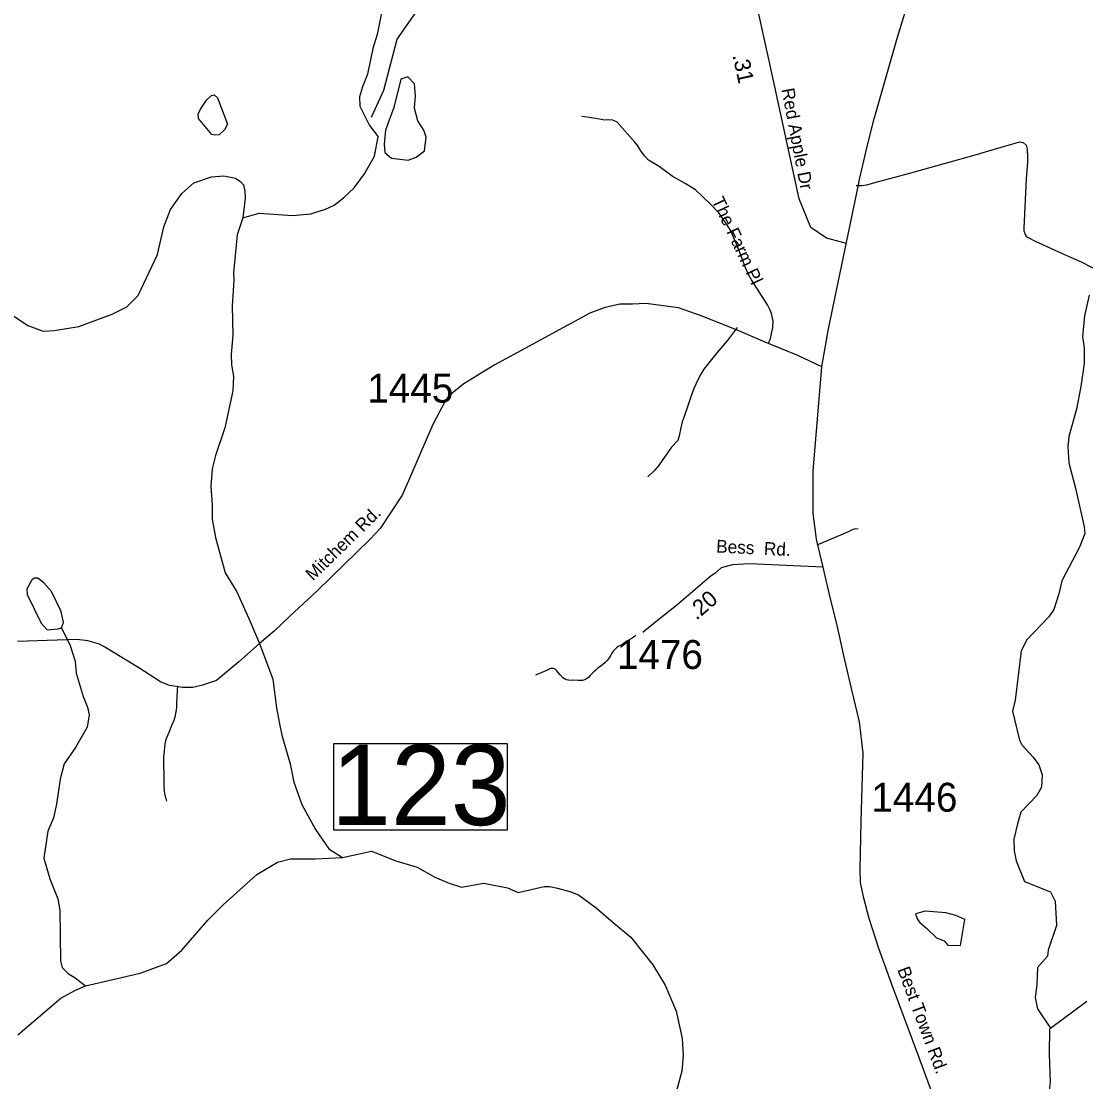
# Model space of a CAD drawing. Extents: x 1268485 to 1426702, y 514839 to 616766.
# Drawn here: x 1317709 to 1323145, y 579327 to 584743 of the extents above; entities that cross this region are included whole.
import ezdxf

# ---------------------------------------------------------------- set-up
doc = ezdxf.new("R2010")
doc.units = 0
for name, color, linetype in [('Old_Level_10', 7, 'Continuous'), ('Old_Level_11', 7, 'Continuous'), ('Old_Level_17', 7, 'Continuous'), ('Old_Level_31', 7, 'Continuous'), ('Old_Level_32', 7, 'Continuous'), ('Old_Level_35', 7, 'Continuous'), ('Old_Level_50', 7, 'Continuous'), ('Old_Level_59', 7, 'Continuous'), ('Old_Level_62', 7, 'Continuous'), ('Old_Level_8', 7, 'Continuous')]:
    doc.layers.add(name, color=color, linetype=linetype)

msp = doc.modelspace()

# ---------------------------------------------------------------- linework, layer by layer
at = {"layer": 'Old_Level_31'}
msp.add_line((1318926.085, 581564.107), (1318926.085, 581564.107), dxfattribs=at)
msp.add_lwpolyline([(1320191.896, 581051.986), (1319302.932, 581051.986), (1319302.932, 580614.063), (1320191.896, 580614.063), (1320191.896, 581051.986)], dxfattribs=at)
at = {"layer": 'Old_Level_32'}
for points in [[(1321797.997, 582978.324), (1321831.203, 583171.729), (1321983.009, 583898.519), (1321990.349, 583934.525), (1322028.373, 584103.643), (1322063.633, 584244.803), (1322183.303, 584662.401), (1322279.87, 584980.061), (1322315.078, 585068.895), (1322350.496, 585143.263), (1322444.891, 585301.092), (1322460.199, 585319.471), (1322477.038, 585333.257), (1322625.673, 585434.483), (1322656.143, 585455.787), (1322668.712, 585471.139), (1322678.197, 585495.813), (1322678.477, 585533.532)], [(1321922.511, 583608.874), (1321820.665, 583635.648), (1321741.623, 583690.392), (1321680.822, 583836.38), (1321540.979, 584487.239), (1321413.296, 585069.373)], [(1321797.997, 582978.324), (1321675.28, 583035.221), (1321507.425, 583104.427), (1321362.167, 583166.583), (1321181.362, 583239.21), (1321064.493, 583279.625), (1320898.163, 583302.008), (1320830.807, 583298.945), (1320764.982, 583297.412), (1320689.972, 583280.565), (1320611.901, 583252.996), (1320380.865, 583127.084), (1320124.185, 582987.109), (1319969.076, 582891.199), (1319903.251, 582839.121), (1319872.636, 582799.297), (1319812.817, 582687.829), (1319782.304, 582617.088), (1319687.186, 582395.092), (1319653.496, 582321.934), (1319541.862, 582152.37), (1319491.345, 582098.763), (1319220.391, 581833.791), (1319081.087, 581705.134), (1318999.954, 581628.553), (1318926.236, 581564.261)], [(1321804.234, 581955.031), (1321770.11, 582098.448), (1321768.58, 582112.233), (1321752.952, 582229.38), (1321752.952, 582445.276), (1321797.997, 582978.324)], [(1321804.234, 581955.031), (1321425.679, 581972.547), (1321340.363, 581966.035), (1321283.454, 581951.799), (1321251.059, 581922.407), (1321231.879, 581910.366), (1321221.164, 581902.709), (1321054.305, 581758.735), (1320957.293, 581683.197), (1320893.498, 581629.393), (1320882.453, 581621.815)], [(1322370.126, 579241.192), (1322298.24, 579440.453), (1322152.813, 579829.181), (1322088.856, 580006.879), (1322038.953, 580160.293), (1322011.677, 580264.91), (1321994.068, 580344.74), (1321993.492, 580412.74), (1321998.19, 580656.613), (1322007.461, 581004.471), (1321988.917, 581164.406), (1321949.766, 581328.338), (1321907.883, 581509.994), (1321875.291, 581659.054), (1321841.195, 581793.237), (1321804.234, 581955.031)], [(1318926.236, 581564.261), (1318820.771, 581472.28), (1318705.378, 581376.32), (1318635.318, 581352.329), (1318585.865, 581340.334), (1318532.29, 581340.334), (1318466.432, 581350.909), (1318420.508, 581369.29), (1318308.758, 581441.28), (1318135.776, 581546.969), (1318108.8, 581561.427), (1318048.52, 581579.135), (1317993.411, 581585.262), (1317690.31, 581576.072)]]:
    msp.add_lwpolyline(points, dxfattribs=at)
at = {"layer": 'Old_Level_35'}
for points in [[(1321527.152, 583102.048), (1321534.328, 583122.809), (1321540.275, 583146.442), (1321546.632, 583179.045), (1321548.99, 583210.879), (1321539.66, 583250.813), (1321533.918, 583266.858), (1321519.872, 583294.797), (1321476.606, 583361.336), (1321437.236, 583422.544), (1321422.37, 583450.585), (1321407.914, 583483.803), (1321388.024, 583535.118), (1321367.006, 583592.583), (1321329.994, 583675.374), (1321316.255, 583700.441), (1321290.624, 583738.068), (1321270.529, 583764.059), (1321227.263, 583810.913), (1321151.906, 583881.451), (1321098.49, 583914.208), (1321032.463, 583952.45), (1320966.642, 584001.201), (1320911.893, 584033.189), (1320890.875, 584056.514), (1320872.728, 584081.017), (1320857.041, 584106.085), (1320842.38, 584125.924), (1320751.542, 584228.552), (1320730.524, 584238.497), (1320707.148, 584239.062), (1320688.489, 584237.882), (1320652.297, 584244.854), (1320611.491, 584251.877), (1320571.301, 584257.106)], [(1321972.627, 583904.878), (1322001.54, 583904.007), (1322027.786, 583908.364), (1322067.464, 583918.873), (1322240.425, 583965.83), (1322386.832, 584006.686), (1322440.659, 584021.194), (1322575.275, 584058.513), (1322725.373, 584104.291), (1322808.112, 584127.052), (1322825.234, 584123.976), (1322840.715, 584111.007), (1322846.457, 584089.271), (1322848.097, 584051.542), (1322846.969, 584024.013), (1322840.51, 583938.148), (1322836.102, 583830.393), (1322828.515, 583686.754), (1322829.335, 583672.759), (1322833.743, 583659.379), (1322839.382, 583647.691), (1322847.79, 583640.668), (1322887.16, 583620.573), (1323040.026, 583549.677), (1323121.637, 583513.741)], [(1323121.637, 583513.741), (1323224.265, 583461.607), (1323287.216, 583431.002), (1323402.353, 583378.253), (1323621.348, 583279.931), (1323873.358, 583169.766), (1324167.607, 583024.231), (1324390.396, 582922.73)], [(1321364.34, 583179.353), (1321313.59, 583111.788), (1321271.247, 583061.55), (1321240.284, 583024.538), (1321212.602, 582990.55), (1321194.352, 582965.637), (1321179.486, 582941.133), (1321165.747, 582914.886), (1321143.602, 582866.801), (1321129.966, 582829.995), (1321115.407, 582784.268), (1321093.364, 582724.393), (1321084.137, 582697.941), (1321076.857, 582666.773), (1321069.27, 582625.25), (1321061.376, 582601.106), (1321029.285, 582567.118), (1320984.994, 582504.987), (1320963.771, 582472.948), (1320940.6, 582446.804), (1320909.125, 582416.764)], [(1321773.419, 582068.636), (1321906.6, 582126), (1321932.95, 582136.868), (1321957.863, 582148.812), (1321971.397, 582151.939), (1321983.29, 582151.375)], [(1320847.919, 581607.043), (1320841.047, 581601.117), (1320828.847, 581592.557), (1320816.031, 581585.123), (1320800.755, 581574.051), (1320784.76, 581563.952), (1320768.254, 581554.827), (1320757.796, 581549.547), (1320748.159, 581542.985), (1320739.341, 581535.193), (1320731.755, 581526.325), (1320725.5, 581516.431), (1320720.477, 581505.871), (1320711.659, 581491.979), (1320701.509, 581479.111), (1320690.026, 581467.424), (1320677.416, 581456.915), (1320665.42, 581448.354), (1320654.142, 581439.075), (1320643.48, 581428.925), (1320632.714, 581420.006), (1320622.667, 581410.317), (1320613.234, 581399.808), (1320605.032, 581391.914), (1320595.702, 581385.3), (1320585.45, 581380.123), (1320574.787, 581376.483), (1320552.642, 581375.304), (1320525.78, 581377.713), (1320515.014, 581376.688), (1320504.249, 581377.457), (1320493.792, 581379.815), (1320483.744, 581383.814), (1320474.517, 581389.299), (1320461.598, 581404.524), (1320443.041, 581427.798), (1320439.658, 581431.129), (1320435.659, 581433.898), (1320431.353, 581436), (1320426.74, 581437.383), (1320422.023, 581437.999), (1320417.102, 581437.896), (1320412.386, 581437.025), (1320407.875, 581435.385), (1320403.774, 581433.077), (1320399.878, 581430.104), (1320335.799, 581403.294)], [(1318506.119, 581348.545), (1318504.991, 581324.964), (1318503.761, 581288.516), (1318502.326, 581261.398), (1318501.711, 581242.174), (1318499.968, 581224.488), (1318497.097, 581206.957), (1318492.996, 581189.63), (1318487.87, 581172.61), (1318480.488, 581152.771), (1318471.876, 581132.881), (1318463.981, 581113.709), (1318456.907, 581098.894), (1318450.858, 581083.618), (1318446.244, 581067.88), (1318442.861, 581051.835), (1318440.708, 581035.584), (1318438.144, 581014.976), (1318436.094, 580983.86), (1318435.479, 580943.515), (1318436.914, 580898.456), (1318437.529, 580837.504), (1318439.477, 580811.001), (1318442.758, 580789.829), (1318446.757, 580772.605), (1318451.37, 580759.994)]]:
    msp.add_lwpolyline(points, dxfattribs=at)
at = {"layer": 'Old_Level_50'}
msp.add_line((1318926.085, 581564.107), (1318926.085, 581564.107), dxfattribs=at)
at = {"layer": 'Old_Level_59'}
for points in [[(1319497.432, 584253.06), (1319561.021, 584390.904), (1319628.677, 584651.421), (1319732.638, 584800.392), (1320166.631, 585182.199), (1320355.689, 585418.009), (1320478.129, 585631.889), (1320563.837, 585881.645), (1320625.999, 586099.358), (1320641.634, 586246.06), (1320773.688, 586542.052), (1320883.596, 586983.017), (1321103.616, 587126.246), (1321174.667, 587308.64), (1321501.623, 587725.511), (1321515.669, 587977.981), (1321654.591, 588231.221), (1322006.666, 588650.86), (1322041.627, 588748.618), (1322050.65, 589116.071), (1322203.003, 589562.521)], [(1318839.739, 583739.503), (1318924.22, 583763.546), (1319094.106, 583751.601), (1319188.43, 583759.393), (1319262.966, 583783.744), (1319307.463, 583804.659), (1319354.42, 583841.619), (1319409.681, 583892.369), (1319461.252, 583963.164), (1319513.335, 584054.053), (1319531.79, 584153.657)], [(1318839.739, 583739.503), (1318811.647, 583652.151), (1318793.09, 583458.428), (1318794.217, 583418.392), (1318785.298, 583290.491), (1318789.706, 583142.341), (1318781.402, 583040.532), (1318782.222, 582988.449), (1318792.885, 582930.214), (1318789.091, 582856.19), (1318748.593, 582667.081), (1318701.431, 582526.057), (1318683.797, 582456.441), (1318677.645, 582366.577), (1318684.688, 582273.661), (1318684.688, 582199.488), (1318701.38, 582106.59), (1318751.016, 581926.219), (1318809.541, 581828.623), (1318871.966, 581691.988), (1318926.236, 581564.261), (1318993.111, 581382.318), (1319012.453, 581237.132), (1319028.059, 581155.151), (1319039.764, 581096.594), (1319081.738, 580949.972), (1319100.202, 580857.59), (1319141.764, 580743.152), (1319211.993, 580614.325), (1319278.858, 580515.572), (1319349.909, 580471.845)], [(1318037.883, 579815.986), (1318315.626, 579881.551), (1318450.858, 579930.456), (1318528.47, 579998.635), (1318662.164, 580151.656), (1318739.981, 580229.883), (1318911.61, 580385.979), (1319017.109, 580447.546), (1319083.648, 580466.052), (1319209.653, 580465.129), (1319349.909, 580471.845)], [(1319349.909, 580471.845), (1319496.906, 580504.856), (1319621.705, 580455.491), (1319731.003, 580422.875), (1319820.74, 580372.126), (1319894.871, 580340.894), (1319957.297, 580321.375), (1320070.444, 580340.894), (1320191.394, 580317.472), (1320246.294, 580292.937), (1320379.065, 580323.848), (1320409.003, 580323.13), (1320446.937, 580316.261), (1320510.503, 580298.781), (1320554.179, 580281.71), (1320644.71, 580215.581), (1320730.934, 580139.609), (1320821.26, 580065.38), (1320934.038, 579924.714), (1320997.707, 579819.215), (1321052.559, 579687.828), (1321083.316, 579547.008), (1321089.263, 579460.836), (1321081.471, 579380.968), (1321031.028, 579192.063)], [(1317691.96, 579565.925), (1317910.34, 579752.932), (1317983.339, 579793.225), (1318037.883, 579815.986)]]:
    msp.add_lwpolyline(points, dxfattribs=at)
at = {"layer": 'Old_Level_62'}
for points in [[(1319553.013, 584811.515), (1319525.843, 584676.079), (1319504.21, 584604.567), (1319477.143, 584473.129), (1319451.614, 584407.665), (1319436.338, 584357.992), (1319437.363, 584309.907), (1319486.986, 584210.713), (1319531.79, 584153.657)], [(1319768.313, 584080.68), (1319776.117, 584150.949), (1319764.411, 584186.084), (1319733.766, 584235.011), (1319717.592, 584299.295), (1319721.494, 584361.757), (1319717.592, 584424.218), (1319682.478, 584459.353), (1319647.364, 584447.641), (1319612.249, 584303.199), (1319569.331, 584186.084), (1319561.528, 584115.815), (1319565.429, 584072.873), (1319599.252, 584044.057), (1319684.964, 584034.06), (1319725.396, 584049.449), (1319768.313, 584080.68)], [(1318694.255, 584367.219), (1318711.889, 584352.814), (1318762.742, 584217.531), (1318746.133, 584187.952), (1318719.476, 584162.526), (1318697.33, 584161.09), (1318681.541, 584165.396), (1318613.361, 584247.007), (1318611.824, 584269.102), (1318624.537, 584294.784), (1318655.602, 584340.152), (1318680.106, 584363.579), (1318694.255, 584367.219)], [(1317634.033, 583263.27), (1317742.198, 583188.733), (1317821.758, 583160.846), (1317877.737, 583163.564), (1318002.409, 583184.684), (1318173.832, 583246.763), (1318248.779, 583285.005), (1318306.091, 583341.702), (1318405.131, 583551.522), (1318436.402, 583692.803), (1318470.543, 583782.051), (1318528.367, 583862.842), (1318589.78, 583917.437), (1318680.516, 583949.323), (1318742.647, 583953.885), (1318802.419, 583942.505), (1318829.999, 583923.845), (1318843.635, 583907.543), (1318850.914, 583875.35), (1318852.042, 583839.261), (1318839.739, 583739.503)], [(1323162.955, 583344.778), (1323138.451, 583239.279), (1323127.891, 583131.473), (1323136.605, 583075.186), (1323136.81, 582995.216), (1323120.099, 582877.516), (1323097.338, 582762.02), (1323058.07, 582622.789), (1323052.842, 582568.912), (1323058.891, 582488.685), (1323093.852, 582351.813), (1323137.323, 582160.756), (1323139.913, 582127.294), (1323112.602, 582057.025), (1323022.801, 581885.217), (1323007.32, 581819.55), (1322981.483, 581738.092), (1322956.57, 581700.67), (1322843.688, 581583.227), (1322814.469, 581527.863), (1322784.531, 581276.418), (1322771.203, 581218.747), (1322805.856, 581071.827), (1322819.185, 581047.477), (1322875.779, 580984.167), (1322904.897, 580945.463), (1322921.711, 580895.021), (1322918.225, 580831.044), (1322895.362, 580789.573), (1322813.238, 580703.451), (1322795.809, 580643.832), (1322777.969, 580566.22), (1322778.584, 580506.139), (1322789.452, 580455.902), (1322832.923, 580348.762), (1322964.823, 580296), (1322988.232, 580249.154), (1322996.036, 580124.231), (1322953.117, 579999.309), (1322949.216, 579968.078), (1322898.495, 579909.52), (1322894.593, 579823.636), (1322886.79, 579757.27), (1322898.495, 579698.712), (1322965.282, 579600.702)], [(1317914.544, 581645.819), (1317925.104, 581671.655), (1317912.391, 581727.942), (1317862.768, 581831.135), (1317823.706, 581874.093), (1317794.281, 581898.751), (1317774.288, 581899.263), (1317761.985, 581887.524), (1317736.969, 581842.105), (1317738.404, 581816.064), (1317810.89, 581668.272), (1317842.161, 581635.515), (1317898.345, 581640.282), (1317914.544, 581645.819)], [(1317914.544, 581645.819), (1317958.425, 581554.827), (1317984.467, 581474.139), (1317989.08, 581414.007), (1318024.349, 581295.129), (1318047.11, 581240.585), (1318056.132, 581200.343), (1318049.263, 581158.462), (1318044.752, 581138.572), (1317986.21, 581033.841), (1317928.282, 580951.154), (1317908.392, 580871.594), (1317889.528, 580743.949), (1317873.841, 580674.282), (1317844.211, 580606.922), (1317825.039, 580469.333), (1317854.464, 580362.552), (1317896.294, 580261.564), (1317906.855, 580203.227), (1317908.905, 579945.066), (1317918.132, 579910.822), (1317949.403, 579880.064), (1317984.877, 579857.252), (1318037.883, 579815.986)], [(1322504.431, 580022.732), (1322527.806, 580155.189), (1322482.182, 580176.257), (1322430.611, 580189.432), (1322324.599, 580197.942), (1322276.309, 580185.075), (1322285.941, 580155.463), (1322297.646, 580139.847), (1322332.76, 580108.616), (1322383.481, 580061.77), (1322422.498, 580046.154), (1322440.659, 580025.134), (1322504.431, 580022.732)], [(1322965.282, 579600.702), (1323150.959, 579739.091)], [(1322959.921, 579598.85), (1322958.793, 579466.797), (1322963.509, 579324.593), (1322948.848, 579214.942), (1322927.01, 579135.33), (1322887.025, 579046.235), (1322857.087, 578970.93), (1322832.174, 578925.459), (1322804.594, 578864.046), (1322759.585, 578735.018), (1322729.032, 578621.726), (1322711.705, 578572.104), (1322692.841, 578534.477), (1322645.269, 578461.529), (1322583.548, 578390.94), (1322546.126, 578331.783), (1322503.338, 578287.643), (1322466.375, 578222.923), (1322424.793, 578158.202), (1322410.933, 578070.367), (1322383.211, 577982.532), (1322360.11, 577853.091)]]:
    msp.add_lwpolyline(points, dxfattribs=at)

# ---------------------------------------------------------------- texts
at = {"layer": 'Old_Level_10'}
msp.add_text('The Farm Pl', height=65.61666, rotation=295.293733, dxfattribs=at).set_placement((1321233.396, 583827.72))
at = {"layer": 'Old_Level_11'}
for s, height, rotation, p in [('Red Apple Dr', 65.61666, 280.770169, (1321590.686, 584395.664)), ('Mitchem Rd.', 65.61666, 44.360517, (1319199.049, 581881.668)), ('Bess  Rd.', 65.6167, 357.350722, (1321256.642, 582029.706)), ('Best Town Rd.', 65.61666, 290.511331, (1322181.612, 579899.986))]:
    msp.add_text(s, height=height, rotation=rotation, dxfattribs=at).set_placement(p)
at = {"layer": 'Old_Level_17'}
for s, rotation, p in [('.31', 282.371103, (1321340.421, 584569.059)), ('.20', 40.789122, (1321157.138, 581681.349))]:
    msp.add_text(s, height=82.0208, rotation=rotation, dxfattribs=at).set_placement(p)
at = {"layer": 'Old_Level_31'}
msp.add_text('123', height=410.1042, dxfattribs=at).set_placement((1319292.33, 580637.595))
at = {"layer": 'Old_Level_8'}
for s, p in [('1445', (1319475.908, 582795.562)), ('1476', (1320750.656, 581435.234)), ('1446', (1322050.257, 580706.09))]:
    msp.add_text(s, height=147.6375, dxfattribs=at).set_placement(p)

doc.saveas('drawing.dxf')
